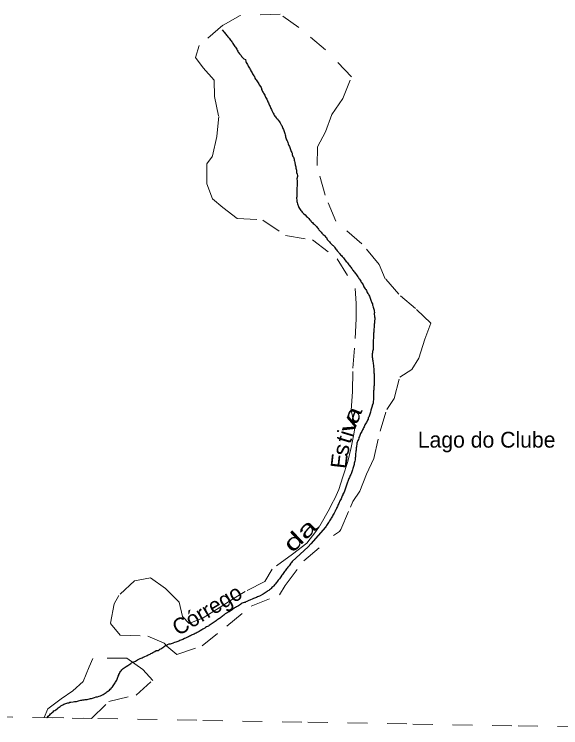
# Model space of a CAD drawing. Extents: x 785.9 to 812.4, y 7674.9 to 7703.1.
# Drawn here: x 788.66 to 791.421, y 7675.261 to 7678.869 of the extents above; entities that cross this region are included whole.
import ezdxf
from ezdxf.enums import TextEntityAlignment as Align

# ---------------------------------------------------------------- set-up
doc = ezdxf.new("R2010")
doc.units = 0
doc.header["$LTSCALE"] = 0.04
doc.linetypes.add('SHORT_DASHED', pattern=[2.7, 1.5, -1.2])
for name, color, linetype, lineweight in [('21', 7, 'SHORT_DASHED', 13), ('53', 7, 'SHORT_DASHED', 13), ('7', 7, 'Continuous', 25)]:
    doc.layers.add(name, color=color, linetype=linetype, lineweight=lineweight)
doc.layers.add('61', color=7, linetype='Continuous')

msp = doc.modelspace()

# ---------------------------------------------------------------- linework, layer by layer
at = {"layer": '21'}
msp.add_line((788.8104, 7675.3123), (789.0507, 7675.3081), dxfattribs=at)
msp.add_lwpolyline([(789.8018, 7678.8632), (789.7131, 7678.8136), (789.5941, 7678.7102), (789.5755, 7678.6493), (789.6141, 7678.598), (789.6693, 7678.5354), (789.6715, 7678.4528), (789.6928, 7678.3519), (789.6837, 7678.251), (789.6616, 7678.151), (789.6333, 7678.1119), (789.632, 7678.011), (789.662, 7677.9362), (789.7137, 7677.891), (789.7863, 7677.8362), (789.9161, 7677.8284), (790.0304, 7677.7501), (790.1663, 7677.7275), (790.2919, 7677.6327), (790.3831, 7677.4823), (790.3875, 7677.4064), (790.3882, 7677.3293), (790.3783, 7677.1797), (790.37, 7677.0623), (790.3686, 7676.9606), (790.363, 7676.8658), (790.3692, 7676.8359), (790.3786, 7676.7941), (790.3792, 7676.7656), (790.3736, 7676.7366), (790.3619, 7676.6774), (790.3457, 7676.6071), (790.3195, 7676.5301), (790.3, 7676.4654), (790.2795, 7676.4209), (790.2644, 7676.3925), (790.2532, 7676.3682), (790.2024, 7676.2804), (790.1841, 7676.2528), (790.1376, 7676.1937), (790.0659, 7676.138), (789.9629, 7676.0632), (789.9251, 7675.9997), (789.8264, 7675.9493), (789.7703, 7675.9163), (789.6951, 7675.8668), (789.6145, 7675.8163), (789.5439, 7675.7882), (789.51, 7675.8234), (789.4937, 7675.8962), (789.4246, 7675.9658), (789.3485, 7676.0197), (789.2673, 7676.004), (789.1879, 7675.9301), (789.164, 7675.8875), (789.1453, 7675.7875), (789.1952, 7675.7292), (789.3347, 7675.724), (789.4167, 7675.6892), (789.4311, 7675.6735), (789.4812, 7675.632), (789.6088, 7675.6753), (789.7334, 7675.7753), (789.8564, 7675.8753), (789.9993, 7675.9336), (790.0288, 7675.9807), (790.1235, 7676.1058), (790.2734, 7676.2328), (790.3026, 7676.2537), (790.3099, 7676.2631), (790.3585, 7676.3757), (790.3699, 7676.4058), (790.4068, 7676.4574), (790.4403, 7676.5436), (790.4763, 7676.6223), (790.5081, 7676.7614), (790.5424, 7676.8701), (790.5801, 7676.9258), (790.6075, 7677.0345), (790.6688, 7677.0719), (790.7039, 7677.1302), (790.7348, 7677.2267), (790.7651, 7677.3075), (790.6879, 7677.3815), (790.6023, 7677.4528), (790.5348, 7677.5312), (790.5041, 7677.6033), (790.4167, 7677.7085), (790.2843, 7677.8233), (790.23, 7677.9537), (790.1904, 7678.1033), (790.1918, 7678.199), (790.233, 7678.2747), (790.2639, 7678.3617), (790.3208, 7678.4426), (790.3638, 7678.553), (790.233, 7678.6895), (790.0979, 7678.8017), (790.0027, 7678.8687)], close=True, dxfattribs=at)
for points in [[(789.2289, 7675.6128), (789.0571, 7675.6115), (789.0378, 7675.5692), (789.0078, 7675.4953), (788.9555, 7675.4481), (788.8974, 7675.4069), (788.8297, 7675.356), (788.8104, 7675.3123)], [(789.0507, 7675.3081), (789.1372, 7675.3941), (789.2749, 7675.4263), (789.3591, 7675.5006), (789.3088, 7675.5547), (789.2289, 7675.6128)]]:
    msp.add_lwpolyline(points, dxfattribs=at)
at = {"layer": '53'}
msp.add_lwpolyline([(785.8981, 7675.3627), (786.4288, 7675.3535), (786.9596, 7675.3444), (787.4903, 7675.3352), (788.021, 7675.326), (788.5518, 7675.3168), (789.0825, 7675.3075), (789.6132, 7675.2983), (790.144, 7675.289), (790.6747, 7675.2798), (791.2055, 7675.2705), (791.7362, 7675.2611)], dxfattribs=at)
at = {"layer": '7'}
for points in [[(789.71, 7678.7894), (789.7189, 7678.7797), (789.7222, 7678.7757), (789.7262, 7678.7716), (789.7294, 7678.7676), (789.7327, 7678.7635), (789.7359, 7678.7595), (789.7391, 7678.7554), (789.7424, 7678.7514), (789.7456, 7678.7474), (789.7489, 7678.7425), (789.7521, 7678.7385), (789.7553, 7678.7344), (789.7586, 7678.7296), (789.7618, 7678.7255), (789.765, 7678.7207), (789.7683, 7678.7158), (789.7748, 7678.7061), (789.778, 7678.702), (789.7804, 7678.6972), (789.7837, 7678.6923), (789.7861, 7678.6875), (789.7893, 7678.6826), (789.7917, 7678.6778), (789.7942, 7678.6729), (789.7974, 7678.6681), (789.8055, 7678.66), (789.8087, 7678.6559), (789.812, 7678.6519), (789.8152, 7678.6478), (789.8193, 7678.6438), (789.8275, 7678.6392), (789.8298, 7678.63), (789.8322, 7678.6252), (789.8354, 7678.6203), (789.8379, 7678.6155), (789.8403, 7678.6106), (789.8419, 7678.6058), (789.8443, 7678.6009), (789.8476, 7678.5969), (789.85, 7678.592), (789.8532, 7678.5871), (789.8557, 7678.5823), (789.8581, 7678.5774), (789.8613, 7678.5726), (789.8638, 7678.5677), (789.867, 7678.5629), (789.8702, 7678.558), (789.8735, 7678.554), (789.8759, 7678.5459), (789.8791, 7678.541), (789.8824, 7678.537), (789.8856, 7678.5321), (789.8888, 7678.5273), (789.8953, 7678.5176), (789.8977, 7678.5127), (789.9042, 7678.503), (789.9066, 7678.4981), (789.9083, 7678.4933), (789.9099, 7678.4884), (789.9123, 7678.4836), (789.9147, 7678.4787), (789.9172, 7678.4739), (789.9196, 7678.469), (789.922, 7678.4642), (789.9253, 7678.4593), (789.9277, 7678.4544), (789.9301, 7678.4496), (789.9333, 7678.4447), (789.9358, 7678.4399), (789.9398, 7678.431), (789.9414, 7678.4261), (789.9439, 7678.4213), (789.9463, 7678.4164), (789.9479, 7678.4116), (789.9503, 7678.4067), (789.9528, 7678.4019), (789.9552, 7678.397), (789.9568, 7678.3921), (789.9592, 7678.3873), (789.9617, 7678.3824), (789.9665, 7678.3727), (789.9681, 7678.3679), (789.9706, 7678.363), (789.973, 7678.3582), (789.9762, 7678.3541), (789.9795, 7678.3493), (789.9835, 7678.3452), (789.9867, 7678.3412)], [(789.9867, 7678.3412), (789.9908, 7678.3379), (789.994, 7678.3339), (789.9973, 7678.3298), (789.9997, 7678.325), (790.0029, 7678.3201), (790.0078, 7678.3104), (790.011, 7678.3056), (790.0134, 7678.3007), (790.0159, 7678.2959), (790.0175, 7678.291), (790.0199, 7678.2861), (790.0215, 7678.2813), (790.0232, 7678.2764), (790.0248, 7678.2708), (790.0264, 7678.2651), (790.028, 7678.2594), (790.0296, 7678.2546), (790.0304, 7678.2489), (790.0337, 7678.2392), (790.0361, 7678.2344), (790.0385, 7678.2295), (790.0402, 7678.2247), (790.0426, 7678.2198), (790.0434, 7678.2141), (790.0458, 7678.2093), (790.0474, 7678.2044), (790.0499, 7678.1996), (790.0523, 7678.1947), (790.0539, 7678.1899), (790.0563, 7678.185), (790.058, 7678.1801), (790.0596, 7678.1753), (790.062, 7678.1704), (790.0636, 7678.1656), (790.0644, 7678.1599), (790.066, 7678.1551), (790.0677, 7678.1502), (790.0709, 7678.1462), (790.0725, 7678.1413), (790.0741, 7678.1365), (790.0749, 7678.1308), (790.0766, 7678.1251), (790.0774, 7678.1195), (790.079, 7678.1073), (790.0814, 7678.1025), (790.0822, 7678.0968), (790.083, 7678.0911), (790.0847, 7678.0863), (790.0855, 7678.0806), (790.0855, 7678.0693), (790.0887, 7678.0596), (790.0903, 7678.0539), (790.0911, 7678.0483), (790.0879, 7678.0361), (790.0895, 7678.0264), (790.0887, 7678.0159), (790.0887, 7677.9989), (790.0879, 7677.9932), (790.0871, 7677.9835), (790.0871, 7677.9455), (790.0863, 7677.9398), (790.0871, 7677.9277), (790.0879, 7677.922), (790.0887, 7677.9164), (790.0903, 7677.9107), (790.0919, 7677.9058), (790.0944, 7677.901), (790.096, 7677.8961), (790.0984, 7677.8913), (790.1008, 7677.8864), (790.1041, 7677.8816), (790.1073, 7677.8767), (790.1105, 7677.8727), (790.1138, 7677.8686), (790.1178, 7677.8646), (790.1211, 7677.8605), (790.1292, 7677.8541), (790.1372, 7677.846), (790.1413, 7677.8427), (790.1445, 7677.8387), (790.1486, 7677.8355), (790.1518, 7677.8314), (790.1559, 7677.8274), (790.1591, 7677.8233), (790.1623, 7677.8193), (790.1664, 7677.8152), (790.1704, 7677.8112), (790.1745, 7677.8079), (790.1866, 7677.7958), (790.1898, 7677.791), (790.1931, 7677.7869), (790.1963, 7677.7829), (790.1996, 7677.7788), (790.2028, 7677.7748), (790.2068, 7677.7707), (790.2101, 7677.7667), (790.2133, 7677.7626), (790.2174, 7677.7586), (790.2214, 7677.7545), (790.2254, 7677.7513)], [(790.2254, 7677.7513), (790.2295, 7677.7481), (790.2327, 7677.744), (790.2368, 7677.74), (790.2392, 7677.7351), (790.2416, 7677.7303), (790.2449, 7677.7262), (790.2489, 7677.7222), (790.2521, 7677.7173), (790.2554, 7677.7133), (790.2594, 7677.7092), (790.2635, 7677.706), (790.2675, 7677.7019), (790.2716, 7677.6987), (790.2756, 7677.6947), (790.2788, 7677.6906), (790.2821, 7677.6866), (790.2853, 7677.6817), (790.2886, 7677.6769), (790.2918, 7677.6728), (790.295, 7677.6688), (790.2991, 7677.6647), (790.3023, 7677.6607), (790.3056, 7677.6566), (790.3088, 7677.6526), (790.3128, 7677.6485), (790.3161, 7677.6445), (790.3201, 7677.6404), (790.3242, 7677.6364), (790.3274, 7677.6324), (790.3306, 7677.6275), (790.3371, 7677.6194), (790.3412, 7677.6154), (790.3444, 7677.6113), (790.3476, 7677.6073), (790.3501, 7677.6024), (790.3533, 7677.5976), (790.3565, 7677.5927), (790.3606, 7677.5895), (790.3638, 7677.5854), (790.3679, 7677.5814), (790.3695, 7677.5765), (790.3727, 7677.5725), (790.3759, 7677.5684), (790.3792, 7677.5644), (790.3824, 7677.5595), (790.3857, 7677.5555), (790.3921, 7677.5458), (790.3954, 7677.5417), (790.3986, 7677.5377), (790.4018, 7677.5328), (790.4051, 7677.5288), (790.4075, 7677.5239), (790.4107, 7677.5191), (790.4132, 7677.5142), (790.4164, 7677.5102), (790.4188, 7677.5053), (790.4221, 7677.5005), (790.4253, 7677.4956), (790.4269, 7677.4908), (790.4334, 7677.481), (790.4358, 7677.4762), (790.4391, 7677.4721), (790.4415, 7677.4673), (790.4439, 7677.4624), (790.4472, 7677.4576), (790.4496, 7677.4527), (790.452, 7677.4479), (790.4544, 7677.443), (790.4561, 7677.4382), (790.4593, 7677.4285), (790.4609, 7677.4236), (790.4633, 7677.4187), (790.465, 7677.4139), (790.4674, 7677.409), (790.4698, 7677.4042), (790.4706, 7677.3985), (790.4722, 7677.3937), (790.4739, 7677.388), (790.4755, 7677.3831), (790.4763, 7677.3775), (790.4779, 7677.3726), (790.4787, 7677.367), (790.4795, 7677.3613), (790.4787, 7677.3556), (790.4787, 7677.35), (790.4795, 7677.3443), (790.4803, 7677.3386), (790.4819, 7677.3338), (790.4819, 7677.3281), (790.4803, 7677.3176), (790.4803, 7677.3063), (790.4787, 7677.3014), (790.4787, 7677.2901), (790.4779, 7677.2844), (790.4771, 7677.2788), (790.4771, 7677.2618), (790.4755, 7677.2569), (790.4755, 7677.2343), (790.4747, 7677.2286), (790.4739, 7677.2229)], [(790.4739, 7677.2229), (790.4739, 7677.1946), (790.473, 7677.1889), (790.473, 7677.1736), (790.4714, 7677.1687), (790.4706, 7677.1631), (790.4698, 7677.1574), (790.469, 7677.1517), (790.469, 7677.1347), (790.4706, 7677.1291), (790.4706, 7677.1234), (790.4722, 7677.1177), (790.4722, 7677.1121), (790.4739, 7677.1064), (790.4739, 7677.1008), (790.4747, 7677.0951), (790.4755, 7677.0894), (790.4755, 7677.0838), (790.4763, 7677.0781), (790.4771, 7677.0724), (790.4771, 7677.0554), (790.4779, 7677.0498), (790.4787, 7677.0441), (790.4787, 7677.0045), (790.4779, 7676.9988), (790.4779, 7676.9923), (790.4771, 7676.9867), (790.4771, 7676.9697), (790.4755, 7676.9648), (790.4755, 7676.9365), (790.4747, 7676.93), (790.4747, 7676.9187), (790.4739, 7676.913), (790.4739, 7676.9074), (790.473, 7676.9017), (790.4714, 7676.8968), (790.469, 7676.892), (790.4682, 7676.8863), (790.4666, 7676.8815), (790.465, 7676.8766), (790.4633, 7676.8718), (790.4617, 7676.8669), (790.4593, 7676.8564), (790.4577, 7676.8515), (790.4561, 7676.8467), (790.4544, 7676.8418), (790.4512, 7676.8321), (790.4488, 7676.8273), (790.448, 7676.8216), (790.4447, 7676.8167), (790.4431, 7676.8119), (790.4399, 7676.807), (790.4374, 7676.8022), (790.435, 7676.7973), (790.4318, 7676.7925), (790.4293, 7676.7876), (790.4277, 7676.7828), (790.4253, 7676.7779), (790.4221, 7676.773), (790.4196, 7676.7682), (790.4172, 7676.7633), (790.4156, 7676.7585), (790.4124, 7676.7536), (790.4099, 7676.7488), (790.4083, 7676.7439), (790.4059, 7676.7391), (790.4043, 7676.7342), (790.4018, 7676.7294), (790.4002, 7676.7245), (790.3986, 7676.7188), (790.3962, 7676.714), (790.3946, 7676.7091), (790.3929, 7676.7043), (790.3905, 7676.6994), (790.3905, 7676.6938), (790.3897, 7676.6873), (790.3889, 7676.6816), (790.3881, 7676.676), (790.3881, 7676.6646), (790.3865, 7676.6598), (790.3857, 7676.6541), (790.3848, 7676.6484), (790.3848, 7676.6371), (790.384, 7676.6314), (790.3824, 7676.6266), (790.3816, 7676.6209), (790.3816, 7676.6153), (790.3808, 7676.6096), (790.3792, 7676.6039), (790.3776, 7676.5983), (790.3768, 7676.5926), (790.3751, 7676.5878), (790.3735, 7676.5821), (790.3719, 7676.5772), (790.3703, 7676.5724), (790.3695, 7676.5659), (790.3679, 7676.5602), (790.3646, 7676.5505), (790.3622, 7676.5457), (790.3598, 7676.5408), (790.3573, 7676.536)], [(790.3573, 7676.536), (790.3549, 7676.5311), (790.3533, 7676.5263), (790.3509, 7676.5214), (790.3484, 7676.5165), (790.3468, 7676.5117), (790.3452, 7676.5068), (790.3436, 7676.502), (790.3412, 7676.4971), (790.3395, 7676.4923), (790.3363, 7676.4826), (790.3347, 7676.4777), (790.3331, 7676.4729), (790.3314, 7676.468), (790.3298, 7676.4631), (790.3282, 7676.4575), (790.3266, 7676.4526), (790.3242, 7676.4478), (790.3209, 7676.4429), (790.3193, 7676.4381), (790.3169, 7676.4332), (790.3145, 7676.4284), (790.3128, 7676.4235), (790.3112, 7676.4186), (790.3088, 7676.4138), (790.3056, 7676.4089), (790.3031, 7676.4041), (790.3015, 7676.3992), (790.2991, 7676.3944), (790.2966, 7676.3895), (790.2942, 7676.3847), (790.2926, 7676.3798), (790.2902, 7676.3749), (790.2877, 7676.3701), (790.2861, 7676.3652), (790.2837, 7676.3604), (790.2821, 7676.3555), (790.2756, 7676.3458), (790.2732, 7676.341), (790.2699, 7676.3353), (790.2675, 7676.3304), (790.2643, 7676.3264), (790.2619, 7676.3215), (790.2594, 7676.3167), (790.253, 7676.307), (790.2505, 7676.3021), (790.2473, 7676.2981), (790.2441, 7676.2932), (790.2408, 7676.2892), (790.2376, 7676.2843), (790.2352, 7676.2795), (790.2319, 7676.2746), (790.1578, 7676.1912), (790.1447, 7676.1753), (790.0644, 7676.1015), (790.0612, 7676.0974), (790.058, 7676.0934), (790.0515, 7676.0853), (790.0482, 7676.0804), (790.045, 7676.0764), (790.0418, 7676.0723), (790.0385, 7676.0683), (790.0353, 7676.0642), (790.0288, 7676.0545), (790.0256, 7676.0505), (790.0224, 7676.0456), (790.0191, 7676.0416), (790.0159, 7676.0367)], [(790.0159, 7676.0367), (790.0126, 7676.0319), (790.0062, 7676.0238), (790.0029, 7676.0189), (790.0005, 7676.0141), (789.9973, 7676.01), (789.9932, 7676.0068), (789.99, 7676.0019), (789.9867, 7675.9979), (789.9827, 7675.9938), (789.9803, 7675.989), (789.9762, 7675.9849), (789.9698, 7675.9769), (789.9657, 7675.9728), (789.9617, 7675.9696), (789.9584, 7675.9655), (789.9544, 7675.9623), (789.9495, 7675.959), (789.9455, 7675.9558), (789.9414, 7675.9526), (789.9374, 7675.9493), (789.9325, 7675.9461), (789.9277, 7675.9429), (789.9228, 7675.9396), (789.918, 7675.9364), (789.8986, 7675.9267), (789.8937, 7675.9251), (789.8888, 7675.9226), (789.884, 7675.9202), (789.8791, 7675.9186), (789.8743, 7675.917), (789.8694, 7675.9145), (789.8646, 7675.9129), (789.85, 7675.9056), (789.8451, 7675.904), (789.8354, 7675.8992), (789.8306, 7675.8976), (789.8257, 7675.8951), (789.8209, 7675.8935), (789.816, 7675.8919), (789.8112, 7675.8903), (789.8071, 7675.887), (789.8023, 7675.8838), (789.7974, 7675.8806), (789.7926, 7675.8773), (789.7828, 7675.8725), (789.778, 7675.8692), (789.7731, 7675.8668), (789.7691, 7675.8636), (789.7642, 7675.8603), (789.7602, 7675.8571), (789.7553, 7675.8539), (789.7456, 7675.8474), (789.7408, 7675.845), (789.7359, 7675.8417), (789.7262, 7675.8369), (789.7222, 7675.8336), (789.7181, 7675.8304), (789.7141, 7675.8272), (789.71, 7675.8239), (789.706, 7675.8207), (789.7011, 7675.8174), (789.6971, 7675.8142), (789.693, 7675.811), (789.6882, 7675.8077), (789.6833, 7675.8045), (789.6793, 7675.8013), (789.6744, 7675.798), (789.6696, 7675.7948), (789.6647, 7675.7916), (789.6599, 7675.7883), (789.655, 7675.7851), (789.6453, 7675.7786), (789.6412, 7675.7754), (789.6315, 7675.7705), (789.6267, 7675.7673), (789.6226, 7675.764), (789.6129, 7675.7592), (789.6081, 7675.756), (789.5984, 7675.7511), (789.5935, 7675.7479), (789.5838, 7675.743), (789.5789, 7675.7398), (789.5741, 7675.7382), (789.5692, 7675.7349), (789.5644, 7675.7325), (789.5595, 7675.7301), (789.5547, 7675.7284), (789.5498, 7675.7252), (789.545, 7675.7236), (789.5401, 7675.7204), (789.5352, 7675.7187), (789.5255, 7675.7139), (789.5207, 7675.7123), (789.511, 7675.7074), (789.5013, 7675.7042), (789.4964, 7675.7017), (789.4916, 7675.6993), (789.4867, 7675.6977), (789.4818, 7675.6961), (789.464, 7675.6896)], [(788.9203, 7675.3837), (788.9252, 7675.3854), (788.9308, 7675.3862), (788.9357, 7675.3878), (788.9405, 7675.3902), (788.9462, 7675.391), (788.9575, 7675.3926), (788.9632, 7675.3935), (788.9688, 7675.3943), (788.9745, 7675.3943), (788.9794, 7675.3959), (788.985, 7675.3967), (788.9955, 7675.3999), (789.0012, 7675.4007), (789.0069, 7675.4015), (789.0125, 7675.4015), (789.0174, 7675.4032), (789.0287, 7675.404), (789.0336, 7675.4056), (789.0392, 7675.4072), (789.0441, 7675.4088), (789.0498, 7675.4088), (789.0595, 7675.4121), (789.0643, 7675.4137), (789.074, 7675.4169), (789.0797, 7675.4177), (789.0894, 7675.421), (789.0951, 7675.4226), (789.1048, 7675.4274), (789.1096, 7675.4299), (789.1145, 7675.4323), (789.1193, 7675.4355), (789.1234, 7675.4388), (789.1274, 7675.442), (789.1323, 7675.4452), (789.1363, 7675.4485), (789.1404, 7675.4517), (789.1444, 7675.4558), (789.1485, 7675.4598), (789.1517, 7675.4647), (789.1558, 7675.4687), (789.159, 7675.4736), (789.1622, 7675.4776), (789.1655, 7675.4825), (789.1687, 7675.4873), (789.1711, 7675.4922), (789.1744, 7675.497), (789.1776, 7675.5011), (789.1792, 7675.5059), (789.1808, 7675.5116), (789.1833, 7675.5164), (789.1849, 7675.5213), (789.1873, 7675.5262), (789.1889, 7675.531), (789.1906, 7675.5359), (789.1938, 7675.5399), (789.197, 7675.5448), (789.1995, 7675.5496), (789.2027, 7675.5545), (789.2067, 7675.5577), (789.2108, 7675.561), (789.2148, 7675.5642), (789.2197, 7675.5666), (789.2245, 7675.5699), (789.2342, 7675.5763), (789.2391, 7675.5796), (789.2431, 7675.5828), (789.248, 7675.5852), (789.2529, 7675.5885), (789.2723, 7675.5982), (789.2771, 7675.6014), (789.282, 7675.6038), (789.2917, 7675.6087), (789.2965, 7675.6111), (789.3014, 7675.6135), (789.3063, 7675.6152), (789.3111, 7675.6176), (789.3168, 7675.6192), (789.3313, 7675.6265), (789.3362, 7675.6297), (789.3411, 7675.6313), (789.3459, 7675.6338), (789.35, 7675.637), (789.3548, 7675.6386), (789.3605, 7675.6411), (789.3702, 7675.6459), (789.3775, 7675.6508), (789.3864, 7675.6524), (789.3912, 7675.6556), (789.3961, 7675.658), (789.4009, 7675.6597), (789.4058, 7675.6629), (789.4098, 7675.6669), (789.4147, 7675.6702), (789.4195, 7675.6734), (789.4236, 7675.6767), (789.4284, 7675.6783), (789.4333, 7675.6815), (789.443, 7675.6848), (789.4487, 7675.6856), (789.464, 7675.6896)], [(788.8236, 7675.312), (788.8256, 7675.3134), (788.8281, 7675.315), (788.8313, 7675.319), (788.8394, 7675.3271), (788.8434, 7675.3312), (788.8475, 7675.3352), (788.8515, 7675.3384), (788.8564, 7675.3417), (788.8604, 7675.3457), (788.8653, 7675.349), (788.8693, 7675.3522), (788.8774, 7675.3587), (788.8815, 7675.3619), (788.8863, 7675.3651), (788.8912, 7675.3684), (788.8952, 7675.3716), (788.9049, 7675.3765), (788.9098, 7675.3797), (788.9146, 7675.3821), (788.9203, 7675.3837)]]:
    msp.add_lwpolyline(points, dxfattribs=at)

# ---------------------------------------------------------------- texts
at = {"layer": '61'}
for s, rotation, width, p in [('a', 68.137, 1.35, (790.4057, 7676.8282)), ('v', 68.137, 1.6, (790.3868, 7676.7807)), ('t', 73.287, 1.05, (790.3626, 7676.7077)), ('s', 78.437, 1.1, (790.3508, 7676.659)), ('E', 83.587, 1.05, (790.3412, 7676.605)), ('da', 44.413, 1.55, (790.1312, 7676.2063))]:
    msp.add_text(s, height=0.08, rotation=rotation, dxfattribs=dict(at, width=width)).set_placement(p, align=Align.CENTER)
for s, rotation, p in [('i', 73.287, (790.3718, 7676.7385)), ('Córrego', 30.878, (789.6543, 7675.8225))]:
    msp.add_text(s, height=0.08, rotation=rotation, dxfattribs=at).set_placement(p, align=Align.CENTER)
msp.add_text('Lago do Clube', height=0.08, dxfattribs=at).set_placement((790.6988, 7676.6774))

doc.saveas('drawing.dxf')
